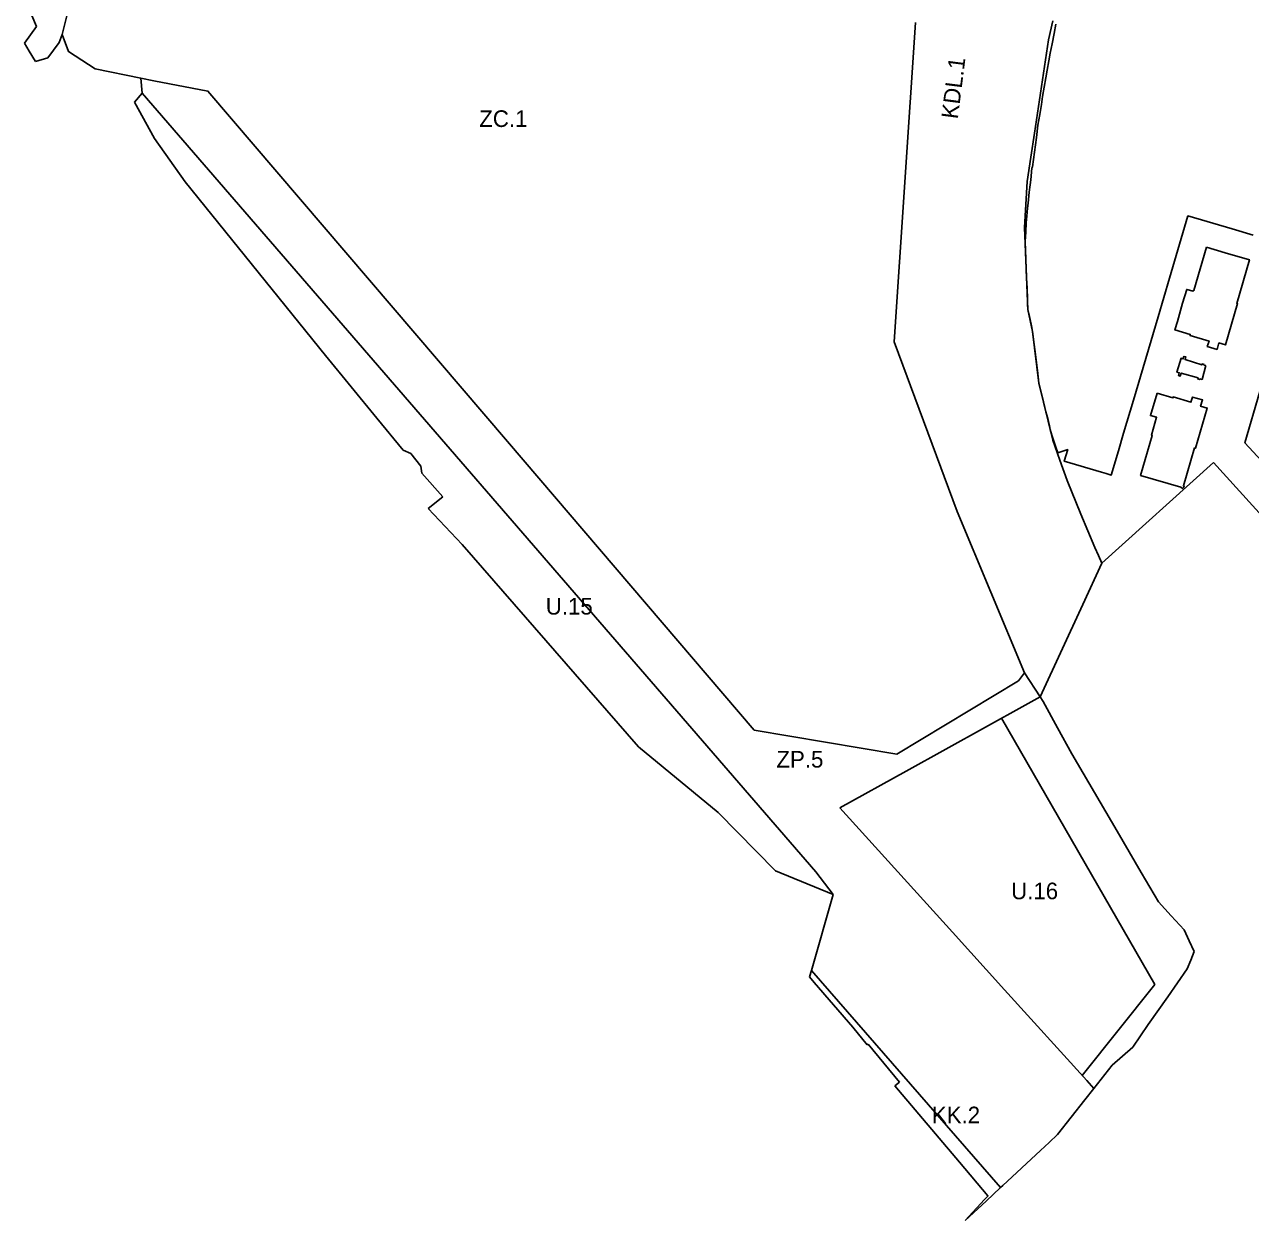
# Model space of a CAD drawing. Extents: x 7424052 to 7425705, y 5546602 to 5547569.
# Drawn here: x 7424796.2 to 7425164.6, y 5546601.7 to 5546961.1 of the extents above; entities that cross this region are included whole.
import ezdxf

# ---------------------------------------------------------------- set-up
doc = ezdxf.new("R2010")
doc.units = 0
for name, color, linetype in [('linie rozgraniczające', 7, 'Continuous'), ('nieprzekraczalne linie zabudowy', 7, 'Continuous'), ('obowiazujace linie zabudowy', 7, 'Continuous'), ('przeznaczenia terenów', 7, 'Continuous')]:
    doc.layers.add(name, color=color, linetype=linetype)

msp = doc.modelspace()

# ---------------------------------------------------------------- linework, layer by layer
at = {"layer": 'linie rozgraniczające'}
for p, q in [((7424796.68, 5546967.84), (7424799.75, 5546960.49)), ((7424799.75, 5546960.49), (7424796.17, 5546955.48)), ((7425103.9, 5546956.52), (7425105.21, 5546962.26)), ((7424806.58, 5546955.77), (7424807.51, 5546958.13)), ((7425101.77, 5546942.5), (7425103.9, 5546956.52)), ((7424796.17, 5546955.48), (7424797.52, 5546953.14)), ((7424797.52, 5546953.14), (7424799.42, 5546950.01)), ((7424803.17, 5546951.1), (7424806.58, 5546955.77)), ((7424799.42, 5546950.01), (7424803.17, 5546951.1)), ((7424831.54, 5546940.46), (7424831.08, 5546945.01)), ((7425099.64, 5546928.48), (7425101.77, 5546942.5)), ((7424829.2, 5546937.84), (7424831.54, 5546940.46)), ((7424835.22, 5546926.84), (7424829.2, 5546937.84)), ((7424831.54, 5546940.46), (7425034, 5546706.51)), ((7424844.43, 5546913.87), (7424835.22, 5546926.84)), ((7425098.56, 5546921.22), (7425099.64, 5546928.48)), ((7425097.49, 5546913.97), (7425098.56, 5546921.22)), ((7424886.6, 5546861.68), (7424844.43, 5546913.87)), ((7425097.06, 5546907.03), (7425097.49, 5546913.97)), ((7425096.63, 5546900.1), (7425097.06, 5546907.03)), ((7425097.16, 5546887.8), (7425096.63, 5546900.1)), ((7425097.7, 5546875.5), (7425097.16, 5546887.8)), ((7425098.4, 5546872.2), (7425097.7, 5546875.5)), ((7425099.1, 5546868.91), (7425098.4, 5546872.2)), ((7425101, 5546853.29), (7425099.1, 5546868.91)), ((7424902.06, 5546842.86), (7424886.6, 5546861.68)), ((7425105.19, 5546836.24), (7425101, 5546853.29)), ((7424909.94, 5546833.19), (7424902.06, 5546842.86)), ((7425107.32, 5546830.15), (7425105.19, 5546836.24)), ((7424912.24, 5546832.16), (7424909.94, 5546833.19)), ((7424915.3, 5546828.4), (7424912.24, 5546832.16)), ((7424915.55, 5546826.29), (7424915.3, 5546828.4)), ((7425109.46, 5546824.07), (7425107.32, 5546830.15)), ((7425153.43, 5546829.48), (7425119.92, 5546799.25)), ((7425208.12, 5546769.05), (7425153.43, 5546829.48)), ((7424921.88, 5546819.15), (7424915.55, 5546826.29)), ((7425113.63, 5546814), (7425109.46, 5546824.07)), ((7424917.5, 5546815.62), (7424921.88, 5546819.15)), ((7424927.72, 5546804.84), (7424917.5, 5546815.62)), ((7425117.8, 5546803.94), (7425113.63, 5546814)), ((7424980.66, 5546744.01), (7424927.72, 5546804.84)), ((7425118.86, 5546801.59), (7425117.8, 5546803.94)), ((7425119.92, 5546799.25), (7425118.86, 5546801.59)), ((7425114.14, 5546786.84), (7425119.92, 5546799.25)), ((7425101.36, 5546759.07), (7425114.14, 5546786.84)), ((7425094.9, 5546763.86), (7425096.66, 5546766.32)), ((7425096.66, 5546766.32), (7425101.36, 5546759.07)), ((7425058.3, 5546741.85), (7425094.9, 5546763.86)), ((7425101.36, 5546759.07), (7425096.88, 5546756.58)), ((7425101.36, 5546759.07), (7425102.27, 5546757.66)), ((7425102.27, 5546757.66), (7425106.58, 5546749.77)), ((7425096.88, 5546756.58), (7425061.15, 5546736.76)), ((7425106.58, 5546749.77), (7425110.89, 5546741.88)), ((7425015.45, 5546749.08), (7425058.3, 5546741.85)), ((7425004.64, 5546724.33), (7424980.66, 5546744.01)), ((7425110.89, 5546741.88), (7425117.69, 5546730.27)), ((7425061.15, 5546736.76), (7425041.14, 5546725.66)), ((7425117.69, 5546730.27), (7425124.49, 5546718.66)), ((7425021.86, 5546706.77), (7425004.64, 5546724.33)), ((7425041.14, 5546725.66), (7425074.98, 5546688.29)), ((7425124.49, 5546718.66), (7425131.72, 5546706.29)), ((7425039.18, 5546699.65), (7425021.86, 5546706.77)), ((7425034, 5546706.51), (7425039.18, 5546699.65)), ((7425131.72, 5546706.29), (7425136.89, 5546697.42)), ((7425032.62, 5546676.83), (7425039.18, 5546699.65)), ((7425074.98, 5546688.29), (7425090.66, 5546670.98)), ((7425032.05, 5546674.86), (7425032.62, 5546676.83)), ((7425032.62, 5546676.83), (7425089.47, 5546611.56)), ((7425033.48, 5546673.2), (7425032.05, 5546674.86)), ((7425045.03, 5546659.74), (7425033.48, 5546673.2)), ((7425090.66, 5546670.98), (7425115.35, 5546643.72)), ((7425049.36, 5546654.48), (7425045.03, 5546659.74)), ((7425133.85, 5546660.53), (7425129.19, 5546653.8)), ((7425049.64, 5546654.71), (7425049.36, 5546654.48)), ((7425059.09, 5546643.26), (7425049.64, 5546654.71)), ((7425129.19, 5546653.8), (7425122.96, 5546648.35)), ((7425122.96, 5546648.35), (7425117.47, 5546641.38)), ((7425122.96, 5546648.35), (7425122.96, 5546648.35)), ((7425057.72, 5546642.14), (7425059.09, 5546643.26)), ((7425115.35, 5546643.72), (7425117.47, 5546641.38)), ((7425104.03, 5546625.14), (7425101.46, 5546622.74)), ((7425106.59, 5546627.55), (7425104.03, 5546625.14)), ((7425101.46, 5546622.74), (7425090.16, 5546612.2)), ((7425090.16, 5546612.2), (7425089.47, 5546611.56))]:
    msp.add_line(p, q, dxfattribs=at)
for points in [[(7424812.89, 5546979.91), (7424807.51, 5546958.13), (7424809.38, 5546952.98), (7424817.39, 5546947.86), (7424831.08, 5546945.01)], [(7425096.66, 5546766.32), (7425076.43, 5546814.73), (7425057.52, 5546865.73), (7425063.89, 5546961.78)], [(7424831.08, 5546945.01), (7424835.07, 5546944.24), (7424851.28, 5546941.12), (7424941.28, 5546835.85), (7425015.45, 5546749.08)], [(7425136.89, 5546697.42), (7425140.78, 5546693.22), (7425144.66, 5546689.01)], [(7425144.66, 5546689.01), (7425146.16, 5546685.76), (7425147.67, 5546682.52)], [(7425147.67, 5546682.52), (7425146.62, 5546679.93), (7425145.58, 5546677.35)], [(7425145.58, 5546677.35), (7425139.71, 5546668.94)], [(7425133.85, 5546660.53), (7425139.71, 5546668.94)], [(7425085.66, 5546609.01), (7425085.63, 5546609.05), (7425077.13, 5546619.16), (7425057.72, 5546642.14)], [(7425117.47, 5546641.38), (7425114.78, 5546637.95), (7425106.59, 5546627.55)], [(7425089.47, 5546611.56), (7425085.1, 5546607.48), (7425078.87, 5546601.67)], [(7425078.87, 5546601.67), (7425084.69, 5546607.96), (7425085.66, 5546609.01)]]:
    msp.add_lwpolyline(points, dxfattribs=at)
at = {"layer": 'nieprzekraczalne linie zabudowy'}
for p, q in [((7425135.83, 5546672.63), (7425089.74, 5546752.62)), ((7425113.99, 5546645.22), (7425135.83, 5546672.63))]:
    msp.add_line(p, q, dxfattribs=at)
at = {"layer": 'obowiazujace linie zabudowy'}
for points in [[(7425106.1, 5546961.19), (7425105.56, 5546958.44), (7425104.95, 5546955.3), (7425104.41, 5546952.54), (7425103.97, 5546950.18), (7425103.47, 5546947.43), (7425103.05, 5546945.06), (7425102.57, 5546942.29), (7425102.11, 5546939.51), (7425101.72, 5546937.12), (7425101.25, 5546934.13), (7425100.7, 5546930.92), (7425100.22, 5546927.2), (7425099.04, 5546918.36), (7425098.91, 5546918), (7425098.54, 5546914.47), (7425098.34, 5546912.9), (7425098.1, 5546910.71), (7425097.72, 5546907.41), (7425097.58, 5546905.9), (7425097.35, 5546903.5), (7425097.21, 5546901.5), (7425097.02, 5546898.69), (7425096.89, 5546895.88), (7425096.95, 5546893.27), (7425097.04, 5546890.65), (7425097.16, 5546887.8), (7425097.3, 5546884.72), (7425097.43, 5546881.96), (7425097.57, 5546878.57), (7425097.59, 5546877.18), (7425097.7, 5546875.5), (7425098.05, 5546873.85), (7425098.75, 5546870.56), (7425099.1, 5546868.91), (7425099.57, 5546865), (7425099.86, 5546862.73), (7425100.05, 5546861.1), (7425100.52, 5546857.19), (7425101, 5546853.29), (7425102.05, 5546849.03), (7425103.09, 5546844.76), (7425103.63, 5546842.68), (7425104.14, 5546840.5), (7425104.37, 5546839.37), (7425104.9, 5546837.68), (7425105.49, 5546835.89), (7425106.07, 5546834.15), (7425106.7, 5546832.38), (7425109.68, 5546833.37), (7425108.59, 5546829.89), (7425119.83, 5546826.57), (7425121.21, 5546826.16), (7425122.71, 5546825.72), (7425124.9, 5546833), (7425126.46, 5546838.3), (7425129.41, 5546848.26), (7425136.82, 5546873.31), (7425140.24, 5546884.85), (7425145.79, 5546903.62), (7425159.06, 5546899.72), (7425165.39, 5546897.85)], [(7425151.32, 5546894.18), (7425147.53, 5546881.16), (7425147.38, 5546881.2), (7425147.3, 5546880.94), (7425145.42, 5546881.49), (7425144.16, 5546877.35), (7425142.59, 5546871.92), (7425141.85, 5546869.33), (7425146.48, 5546867.97), (7425146.43, 5546867.63), (7425152.12, 5546865.98), (7425151.57, 5546864.37), (7425154.52, 5546863.47), (7425155.09, 5546865.41), (7425157.08, 5546864.81), (7425160.7, 5546877.26), (7425160.46, 5546877.32), (7425164.27, 5546890.41), (7425156.96, 5546892.54), (7425151.32, 5546894.18)], [(7425151.19, 5546858.6), (7425150.56, 5546858.78), (7425150.61, 5546858.98), (7425150.05, 5546859.14), (7425149.94, 5546858.81), (7425144.94, 5546860.44), (7425145.16, 5546861.21), (7425144.55, 5546861.37), (7425144.35, 5546860.64), (7425143.69, 5546860.83), (7425142.47, 5546856.65), (7425143.14, 5546856.45), (7425142.9, 5546855.65), (7425143.48, 5546855.48), (7425143.75, 5546856.39), (7425148.82, 5546854.9), (7425148.73, 5546854.59), (7425149.32, 5546854.42), (7425149.38, 5546854.62), (7425150, 5546854.44), (7425151.19, 5546858.6)], [(7425136.52, 5546850.34), (7425134.51, 5546843.61), (7425136.37, 5546843.09), (7425134.82, 5546837.71), (7425135.04, 5546837.62), (7425131.56, 5546825.63), (7425143.68, 5546822.11), (7425144.11, 5546821.67), (7425144.66, 5546822.17), (7425144.42, 5546822.44), (7425147.77, 5546833.87), (7425148.05, 5546833.78), (7425151.58, 5546845.84), (7425149.58, 5546846.42), (7425150.15, 5546848.31), (7425147.14, 5546849.17), (7425146.69, 5546847.58), (7425141.34, 5546849.19), (7425141.26, 5546848.92), (7425136.52, 5546850.34)], [(7425167.41, 5546850.8), (7425162.88, 5546835.39), (7425167.84, 5546829.96), (7425167.4, 5546829.56), (7425171.49, 5546825.07), (7425179.69, 5546832.5), (7425175.93, 5546836.6), (7425176.92, 5546837.91), (7425176.51, 5546839.51), (7425175.13, 5546839.89), (7425177.45, 5546848.01), (7425167.41, 5546850.8)]]:
    msp.add_lwpolyline(points, dxfattribs=at)

# ---------------------------------------------------------------- texts
at = {"layer": 'przeznaczenia terenów'}
msp.add_text('KDL.1', height=5, rotation=82.8006, dxfattribs=at).set_placement((7425076.6, 5546932.56))
for s, p in [('ZC.1', (7424932.81, 5546930.34)), ('U.15', (7424952.8, 5546783.78)), ('ZP.5', (7425022.11, 5546737.79)), ('U.16', (7425092.64, 5546698.22)), ('KK.2', (7425068.82, 5546630.88))]:
    msp.add_text(s, height=5, dxfattribs=at).set_placement(p)

doc.saveas('drawing.dxf')
